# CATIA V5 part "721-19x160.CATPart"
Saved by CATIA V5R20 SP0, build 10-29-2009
Part number: 721-19x160
Definition: NONE
Nomenclature: 721-19x160
Source: Unknown
Description: 721-19x160
Bounding box of the stored display mesh (mm): x -70 to 90, y -21 to 21, z -21 to 21
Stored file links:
  C:\Users\Utente\Desktop\IO LAVORO\3D X SITO CF\X SITO\721\721-19x160.CATPart
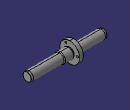
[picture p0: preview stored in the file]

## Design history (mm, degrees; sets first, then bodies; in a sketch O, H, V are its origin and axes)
Body1 "721-19x160" (main body)
  Solid1: solid without history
